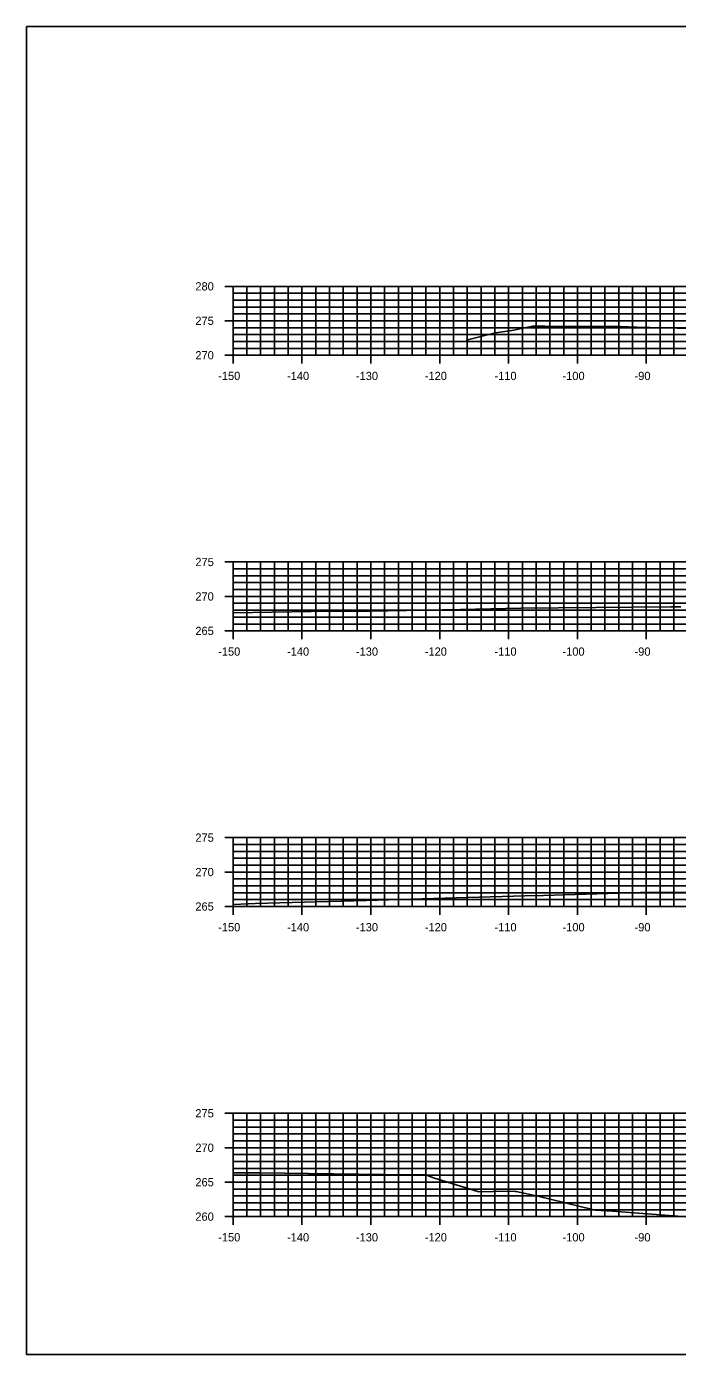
# Model space of a CAD drawing. Extents: x 1661012 to 1662122, y 670053 to 671852.
# Drawn here: x 1661412 to 1661506.5, y 671274.1 to 671466.8 of the extents above; entities that cross this region are included whole.
import ezdxf

# ---------------------------------------------------------------- set-up
doc = ezdxf.new("R2010")
doc.units = 0
for name, color, linetype in [('R_Concrete', 7, 'Continuous'), ('R_Concrete Hidden', 7, 'Continuous'), ('R_Erosion', 7, 'Continuous'), ('R_Exist Surface', 7, 'Continuous'), ('R_Proposed Road', 7, 'Continuous')]:
    doc.layers.add(name, color=color, linetype=linetype)

msp = doc.modelspace()

# ---------------------------------------------------------------- linework, layer by layer
at = {"layer": 'R_Concrete'}
for p, q in [((1661440.79, 671429.12), (1661443.19, 671429.12)), ((1661441.99, 671429.12), (1661741.99, 671429.12)), ((1661441.99, 671419.12), (1661441.99, 671429.12)), ((1661443.99, 671419.12), (1661443.99, 671429.12)), ((1661445.99, 671419.12), (1661445.99, 671429.12)), ((1661447.99, 671419.12), (1661447.99, 671429.12)), ((1661449.99, 671419.12), (1661449.99, 671429.12)), ((1661451.99, 671419.12), (1661451.99, 671429.12)), ((1661453.99, 671419.12), (1661453.99, 671429.12)), ((1661455.99, 671419.12), (1661455.99, 671429.12)), ((1661457.99, 671419.12), (1661457.99, 671429.12)), ((1661459.99, 671419.12), (1661459.99, 671429.12)), ((1661461.99, 671419.12), (1661461.99, 671429.12)), ((1661463.99, 671419.12), (1661463.99, 671429.12)), ((1661465.99, 671419.12), (1661465.99, 671429.12)), ((1661467.99, 671419.12), (1661467.99, 671429.12)), ((1661469.99, 671419.12), (1661469.99, 671429.12)), ((1661471.99, 671419.12), (1661471.99, 671429.12)), ((1661473.99, 671419.12), (1661473.99, 671429.12)), ((1661475.99, 671419.12), (1661475.99, 671429.12)), ((1661477.99, 671419.12), (1661477.99, 671429.12)), ((1661479.99, 671419.12), (1661479.99, 671429.12)), ((1661481.99, 671419.12), (1661481.99, 671429.12)), ((1661483.99, 671419.12), (1661483.99, 671429.12)), ((1661485.99, 671419.12), (1661485.99, 671429.12)), ((1661487.99, 671419.12), (1661487.99, 671429.12)), ((1661489.99, 671419.12), (1661489.99, 671429.12)), ((1661491.99, 671419.12), (1661491.99, 671429.12)), ((1661493.99, 671419.12), (1661493.99, 671429.12)), ((1661495.99, 671419.12), (1661495.99, 671429.12)), ((1661497.99, 671419.12), (1661497.99, 671429.12)), ((1661499.99, 671419.12), (1661499.99, 671429.12)), ((1661501.99, 671419.12), (1661501.99, 671429.12)), ((1661503.99, 671419.12), (1661503.99, 671429.12)), ((1661505.99, 671419.12), (1661505.99, 671429.12)), ((1661441.99, 671428.12), (1661741.99, 671428.12)), ((1661441.99, 671428.12), (1661442.59, 671428.12)), ((1661441.99, 671427.12), (1661741.99, 671427.12)), ((1661441.99, 671427.12), (1661442.59, 671427.12)), ((1661441.99, 671426.12), (1661741.99, 671426.12)), ((1661441.99, 671426.12), (1661442.59, 671426.12)), ((1661441.99, 671425.12), (1661741.99, 671425.12)), ((1661441.99, 671425.12), (1661442.59, 671425.12)), ((1661440.79, 671424.12), (1661443.19, 671424.12)), ((1661441.99, 671424.12), (1661741.99, 671424.12)), ((1661441.99, 671423.12), (1661741.99, 671423.12)), ((1661441.99, 671423.12), (1661442.59, 671423.12)), ((1661441.99, 671422.12), (1661741.99, 671422.12)), ((1661441.99, 671422.12), (1661442.59, 671422.12)), ((1661441.99, 671421.12), (1661741.99, 671421.12)), ((1661441.99, 671421.12), (1661442.59, 671421.12)), ((1661440.79, 671419.12), (1661443.19, 671419.12)), ((1661441.99, 671417.92), (1661441.99, 671420.32)), ((1661441.99, 671420.12), (1661741.99, 671420.12)), ((1661441.99, 671420.12), (1661442.59, 671420.12)), ((1661441.99, 671419.12), (1661741.99, 671419.12)), ((1661443.99, 671419.12), (1661443.99, 671419.72)), ((1661445.99, 671419.12), (1661445.99, 671419.72)), ((1661447.99, 671419.12), (1661447.99, 671419.72)), ((1661449.99, 671419.12), (1661449.99, 671419.72)), ((1661451.99, 671417.92), (1661451.99, 671420.32)), ((1661453.99, 671419.12), (1661453.99, 671419.72)), ((1661455.99, 671419.12), (1661455.99, 671419.72)), ((1661457.99, 671419.12), (1661457.99, 671419.72)), ((1661459.99, 671419.12), (1661459.99, 671419.72)), ((1661461.99, 671417.92), (1661461.99, 671420.32)), ((1661463.99, 671419.12), (1661463.99, 671419.72)), ((1661465.99, 671419.12), (1661465.99, 671419.72)), ((1661467.99, 671419.12), (1661467.99, 671419.72)), ((1661469.99, 671419.12), (1661469.99, 671419.72)), ((1661471.99, 671417.92), (1661471.99, 671420.32)), ((1661473.99, 671419.12), (1661473.99, 671419.72)), ((1661475.99, 671419.12), (1661475.99, 671419.72)), ((1661477.99, 671419.12), (1661477.99, 671419.72)), ((1661479.99, 671419.12), (1661479.99, 671419.72)), ((1661481.99, 671417.92), (1661481.99, 671420.32)), ((1661483.99, 671419.12), (1661483.99, 671419.72)), ((1661485.99, 671419.12), (1661485.99, 671419.72)), ((1661487.99, 671419.12), (1661487.99, 671419.72)), ((1661489.99, 671419.12), (1661489.99, 671419.72)), ((1661491.99, 671417.92), (1661491.99, 671420.32)), ((1661493.99, 671419.12), (1661493.99, 671419.72)), ((1661495.99, 671419.12), (1661495.99, 671419.72)), ((1661497.99, 671419.12), (1661497.99, 671419.72)), ((1661499.99, 671419.12), (1661499.99, 671419.72)), ((1661501.99, 671417.92), (1661501.99, 671420.32)), ((1661503.99, 671419.12), (1661503.99, 671419.72)), ((1661505.99, 671419.12), (1661505.99, 671419.72)), ((1661440.79, 671389.12), (1661443.19, 671389.12)), ((1661441.99, 671389.12), (1661741.99, 671389.12)), ((1661441.99, 671379.12), (1661441.99, 671389.12)), ((1661441.99, 671388.12), (1661741.99, 671388.12)), ((1661441.99, 671388.12), (1661442.59, 671388.12)), ((1661443.99, 671379.12), (1661443.99, 671389.12)), ((1661445.99, 671379.12), (1661445.99, 671389.12)), ((1661447.99, 671379.12), (1661447.99, 671389.12)), ((1661449.99, 671379.12), (1661449.99, 671389.12)), ((1661451.99, 671379.12), (1661451.99, 671389.12)), ((1661453.99, 671379.12), (1661453.99, 671389.12)), ((1661455.99, 671379.12), (1661455.99, 671389.12)), ((1661457.99, 671379.12), (1661457.99, 671389.12)), ((1661459.99, 671379.12), (1661459.99, 671389.12)), ((1661461.99, 671379.12), (1661461.99, 671389.12)), ((1661463.99, 671379.12), (1661463.99, 671389.12)), ((1661465.99, 671379.12), (1661465.99, 671389.12)), ((1661467.99, 671379.12), (1661467.99, 671389.12)), ((1661469.99, 671379.12), (1661469.99, 671389.12)), ((1661471.99, 671379.12), (1661471.99, 671389.12)), ((1661473.99, 671379.12), (1661473.99, 671389.12)), ((1661475.99, 671379.12), (1661475.99, 671389.12)), ((1661477.99, 671379.12), (1661477.99, 671389.12)), ((1661479.99, 671379.12), (1661479.99, 671389.12)), ((1661481.99, 671379.12), (1661481.99, 671389.12)), ((1661483.99, 671379.12), (1661483.99, 671389.12)), ((1661485.99, 671379.12), (1661485.99, 671389.12)), ((1661487.99, 671379.12), (1661487.99, 671389.12)), ((1661489.99, 671379.12), (1661489.99, 671389.12)), ((1661491.99, 671379.12), (1661491.99, 671389.12)), ((1661493.99, 671379.12), (1661493.99, 671389.12)), ((1661495.99, 671379.12), (1661495.99, 671389.12)), ((1661497.99, 671379.12), (1661497.99, 671389.12)), ((1661499.99, 671379.12), (1661499.99, 671389.12)), ((1661501.99, 671379.12), (1661501.99, 671389.12)), ((1661503.99, 671379.12), (1661503.99, 671389.12)), ((1661505.99, 671379.12), (1661505.99, 671389.12)), ((1661441.99, 671387.12), (1661741.99, 671387.12)), ((1661441.99, 671387.12), (1661442.59, 671387.12)), ((1661441.99, 671386.12), (1661741.99, 671386.12)), ((1661441.99, 671386.12), (1661442.59, 671386.12)), ((1661441.99, 671385.12), (1661741.99, 671385.12)), ((1661441.99, 671385.12), (1661442.59, 671385.12)), ((1661440.79, 671384.12), (1661443.19, 671384.12)), ((1661441.99, 671384.12), (1661741.99, 671384.12)), ((1661441.99, 671383.12), (1661741.99, 671383.12)), ((1661441.99, 671383.12), (1661442.59, 671383.12)), ((1661441.99, 671382.12), (1661741.99, 671382.12)), ((1661441.99, 671382.12), (1661442.59, 671382.12)), ((1661441.99, 671381.12), (1661741.99, 671381.12)), ((1661441.99, 671381.12), (1661442.59, 671381.12)), ((1661441.99, 671377.92), (1661441.99, 671380.32)), ((1661451.99, 671377.92), (1661451.99, 671380.32)), ((1661461.99, 671377.92), (1661461.99, 671380.32)), ((1661471.99, 671377.92), (1661471.99, 671380.32)), ((1661481.99, 671377.92), (1661481.99, 671380.32)), ((1661491.99, 671377.92), (1661491.99, 671380.32)), ((1661501.99, 671377.92), (1661501.99, 671380.32)), ((1661440.79, 671379.12), (1661443.19, 671379.12)), ((1661441.99, 671380.12), (1661741.99, 671380.12)), ((1661441.99, 671380.12), (1661442.59, 671380.12)), ((1661441.99, 671379.12), (1661741.99, 671379.12)), ((1661443.99, 671379.12), (1661443.99, 671379.72)), ((1661445.99, 671379.12), (1661445.99, 671379.72)), ((1661447.99, 671379.12), (1661447.99, 671379.72)), ((1661449.99, 671379.12), (1661449.99, 671379.72)), ((1661453.99, 671379.12), (1661453.99, 671379.72)), ((1661455.99, 671379.12), (1661455.99, 671379.72)), ((1661457.99, 671379.12), (1661457.99, 671379.72)), ((1661459.99, 671379.12), (1661459.99, 671379.72)), ((1661463.99, 671379.12), (1661463.99, 671379.72)), ((1661465.99, 671379.12), (1661465.99, 671379.72)), ((1661467.99, 671379.12), (1661467.99, 671379.72)), ((1661469.99, 671379.12), (1661469.99, 671379.72)), ((1661473.99, 671379.12), (1661473.99, 671379.72)), ((1661475.99, 671379.12), (1661475.99, 671379.72)), ((1661477.99, 671379.12), (1661477.99, 671379.72)), ((1661479.99, 671379.12), (1661479.99, 671379.72)), ((1661483.99, 671379.12), (1661483.99, 671379.72)), ((1661485.99, 671379.12), (1661485.99, 671379.72)), ((1661487.99, 671379.12), (1661487.99, 671379.72)), ((1661489.99, 671379.12), (1661489.99, 671379.72)), ((1661493.99, 671379.12), (1661493.99, 671379.72)), ((1661495.99, 671379.12), (1661495.99, 671379.72)), ((1661497.99, 671379.12), (1661497.99, 671379.72)), ((1661499.99, 671379.12), (1661499.99, 671379.72)), ((1661503.99, 671379.12), (1661503.99, 671379.72)), ((1661505.99, 671379.12), (1661505.99, 671379.72)), ((1661440.79, 671349.12), (1661443.19, 671349.12)), ((1661441.99, 671349.12), (1661741.99, 671349.12)), ((1661441.99, 671339.12), (1661441.99, 671349.12)), ((1661441.99, 671348.12), (1661741.99, 671348.12)), ((1661441.99, 671348.12), (1661442.59, 671348.12)), ((1661443.99, 671339.12), (1661443.99, 671349.12)), ((1661445.99, 671339.12), (1661445.99, 671349.12)), ((1661447.99, 671339.12), (1661447.99, 671349.12)), ((1661449.99, 671339.12), (1661449.99, 671349.12)), ((1661451.99, 671339.12), (1661451.99, 671349.12)), ((1661453.99, 671339.12), (1661453.99, 671349.12)), ((1661455.99, 671339.12), (1661455.99, 671349.12)), ((1661457.99, 671339.12), (1661457.99, 671349.12)), ((1661459.99, 671339.12), (1661459.99, 671349.12)), ((1661461.99, 671339.12), (1661461.99, 671349.12)), ((1661463.99, 671339.12), (1661463.99, 671349.12)), ((1661465.99, 671339.12), (1661465.99, 671349.12)), ((1661467.99, 671339.12), (1661467.99, 671349.12)), ((1661469.99, 671339.12), (1661469.99, 671349.12)), ((1661471.99, 671339.12), (1661471.99, 671349.12)), ((1661473.99, 671339.12), (1661473.99, 671349.12)), ((1661475.99, 671339.12), (1661475.99, 671349.12)), ((1661477.99, 671339.12), (1661477.99, 671349.12)), ((1661479.99, 671339.12), (1661479.99, 671349.12)), ((1661481.99, 671339.12), (1661481.99, 671349.12)), ((1661483.99, 671339.12), (1661483.99, 671349.12)), ((1661485.99, 671339.12), (1661485.99, 671349.12)), ((1661487.99, 671339.12), (1661487.99, 671349.12)), ((1661489.99, 671339.12), (1661489.99, 671349.12)), ((1661491.99, 671339.12), (1661491.99, 671349.12)), ((1661493.99, 671339.12), (1661493.99, 671349.12)), ((1661495.99, 671339.12), (1661495.99, 671349.12)), ((1661497.99, 671339.12), (1661497.99, 671349.12)), ((1661499.99, 671339.12), (1661499.99, 671349.12)), ((1661501.99, 671339.12), (1661501.99, 671349.12)), ((1661503.99, 671339.12), (1661503.99, 671349.12)), ((1661505.99, 671339.12), (1661505.99, 671349.12)), ((1661441.99, 671347.12), (1661741.99, 671347.12)), ((1661441.99, 671347.12), (1661442.59, 671347.12)), ((1661441.99, 671346.12), (1661741.99, 671346.12)), ((1661441.99, 671346.12), (1661442.59, 671346.12)), ((1661440.79, 671344.12), (1661443.19, 671344.12)), ((1661441.99, 671345.12), (1661741.99, 671345.12)), ((1661441.99, 671345.12), (1661442.59, 671345.12)), ((1661441.99, 671344.12), (1661741.99, 671344.12)), ((1661441.99, 671343.12), (1661741.99, 671343.12)), ((1661441.99, 671343.12), (1661442.59, 671343.12)), ((1661441.99, 671342.12), (1661741.99, 671342.12)), ((1661441.99, 671342.12), (1661442.59, 671342.12)), ((1661441.99, 671341.12), (1661741.99, 671341.12)), ((1661441.99, 671341.12), (1661442.59, 671341.12)), ((1661441.99, 671337.92), (1661441.99, 671340.32)), ((1661441.99, 671340.12), (1661741.99, 671340.12)), ((1661441.99, 671340.12), (1661442.59, 671340.12)), ((1661451.99, 671337.92), (1661451.99, 671340.32)), ((1661461.99, 671337.92), (1661461.99, 671340.32)), ((1661471.99, 671337.92), (1661471.99, 671340.32)), ((1661481.99, 671337.92), (1661481.99, 671340.32)), ((1661491.99, 671337.92), (1661491.99, 671340.32)), ((1661501.99, 671337.92), (1661501.99, 671340.32)), ((1661440.79, 671339.12), (1661443.19, 671339.12)), ((1661441.99, 671339.12), (1661741.99, 671339.12)), ((1661443.99, 671339.12), (1661443.99, 671339.72)), ((1661445.99, 671339.12), (1661445.99, 671339.72)), ((1661447.99, 671339.12), (1661447.99, 671339.72)), ((1661449.99, 671339.12), (1661449.99, 671339.72)), ((1661453.99, 671339.12), (1661453.99, 671339.72)), ((1661455.99, 671339.12), (1661455.99, 671339.72)), ((1661457.99, 671339.12), (1661457.99, 671339.72)), ((1661459.99, 671339.12), (1661459.99, 671339.72)), ((1661463.99, 671339.12), (1661463.99, 671339.72)), ((1661465.99, 671339.12), (1661465.99, 671339.72)), ((1661467.99, 671339.12), (1661467.99, 671339.72)), ((1661469.99, 671339.12), (1661469.99, 671339.72)), ((1661473.99, 671339.12), (1661473.99, 671339.72)), ((1661475.99, 671339.12), (1661475.99, 671339.72)), ((1661477.99, 671339.12), (1661477.99, 671339.72)), ((1661479.99, 671339.12), (1661479.99, 671339.72)), ((1661483.99, 671339.12), (1661483.99, 671339.72)), ((1661485.99, 671339.12), (1661485.99, 671339.72)), ((1661487.99, 671339.12), (1661487.99, 671339.72)), ((1661489.99, 671339.12), (1661489.99, 671339.72)), ((1661493.99, 671339.12), (1661493.99, 671339.72)), ((1661495.99, 671339.12), (1661495.99, 671339.72)), ((1661497.99, 671339.12), (1661497.99, 671339.72)), ((1661499.99, 671339.12), (1661499.99, 671339.72)), ((1661503.99, 671339.12), (1661503.99, 671339.72)), ((1661505.99, 671339.12), (1661505.99, 671339.72)), ((1661440.79, 671309.12), (1661443.19, 671309.12)), ((1661441.99, 671309.12), (1661741.99, 671309.12)), ((1661441.99, 671294.12), (1661441.99, 671309.12)), ((1661443.99, 671294.12), (1661443.99, 671309.12)), ((1661445.99, 671294.12), (1661445.99, 671309.12)), ((1661447.99, 671294.12), (1661447.99, 671309.12)), ((1661449.99, 671294.12), (1661449.99, 671309.12)), ((1661451.99, 671294.12), (1661451.99, 671309.12)), ((1661453.99, 671294.12), (1661453.99, 671309.12)), ((1661455.99, 671294.12), (1661455.99, 671309.12)), ((1661457.99, 671294.12), (1661457.99, 671309.12)), ((1661459.99, 671294.12), (1661459.99, 671309.12)), ((1661461.99, 671294.12), (1661461.99, 671309.12)), ((1661463.99, 671294.12), (1661463.99, 671309.12)), ((1661465.99, 671294.12), (1661465.99, 671309.12)), ((1661467.99, 671294.12), (1661467.99, 671309.12)), ((1661469.99, 671294.12), (1661469.99, 671309.12)), ((1661471.99, 671294.12), (1661471.99, 671309.12)), ((1661473.99, 671294.12), (1661473.99, 671309.12)), ((1661475.99, 671294.12), (1661475.99, 671309.12)), ((1661477.99, 671294.12), (1661477.99, 671309.12)), ((1661479.99, 671294.12), (1661479.99, 671309.12)), ((1661481.99, 671294.12), (1661481.99, 671309.12)), ((1661483.99, 671294.12), (1661483.99, 671309.12)), ((1661485.99, 671294.12), (1661485.99, 671309.12)), ((1661487.99, 671294.12), (1661487.99, 671309.12)), ((1661489.99, 671294.12), (1661489.99, 671309.12)), ((1661491.99, 671294.12), (1661491.99, 671309.12)), ((1661493.99, 671294.12), (1661493.99, 671309.12)), ((1661495.99, 671294.12), (1661495.99, 671309.12)), ((1661497.99, 671294.12), (1661497.99, 671309.12)), ((1661499.99, 671294.12), (1661499.99, 671309.12)), ((1661501.99, 671294.12), (1661501.99, 671309.12)), ((1661503.99, 671294.12), (1661503.99, 671309.12)), ((1661505.99, 671294.12), (1661505.99, 671309.12)), ((1661441.99, 671308.12), (1661741.99, 671308.12)), ((1661441.99, 671308.12), (1661442.59, 671308.12)), ((1661441.99, 671307.12), (1661741.99, 671307.12)), ((1661441.99, 671307.12), (1661442.59, 671307.12)), ((1661441.99, 671306.12), (1661741.99, 671306.12)), ((1661441.99, 671306.12), (1661442.59, 671306.12)), ((1661440.79, 671304.12), (1661443.19, 671304.12)), ((1661441.99, 671305.12), (1661741.99, 671305.12)), ((1661441.99, 671305.12), (1661442.59, 671305.12)), ((1661441.99, 671304.12), (1661741.99, 671304.12)), ((1661441.99, 671303.12), (1661741.99, 671303.12)), ((1661441.99, 671303.12), (1661442.59, 671303.12)), ((1661441.99, 671302.12), (1661741.99, 671302.12)), ((1661441.99, 671302.12), (1661442.59, 671302.12)), ((1661441.99, 671301.12), (1661741.99, 671301.12)), ((1661441.99, 671301.12), (1661442.59, 671301.12)), ((1661441.99, 671300.12), (1661741.99, 671300.12)), ((1661441.99, 671300.12), (1661442.59, 671300.12)), ((1661440.79, 671299.12), (1661443.19, 671299.12)), ((1661441.99, 671299.12), (1661741.99, 671299.12)), ((1661441.99, 671298.12), (1661741.99, 671298.12)), ((1661441.99, 671298.12), (1661442.59, 671298.12)), ((1661441.99, 671297.12), (1661741.99, 671297.12)), ((1661441.99, 671297.12), (1661442.59, 671297.12)), ((1661441.99, 671296.12), (1661741.99, 671296.12)), ((1661441.99, 671296.12), (1661442.59, 671296.12)), ((1661440.79, 671294.12), (1661443.19, 671294.12)), ((1661441.99, 671292.92), (1661441.99, 671295.32)), ((1661441.99, 671295.12), (1661741.99, 671295.12)), ((1661441.99, 671295.12), (1661442.59, 671295.12)), ((1661441.99, 671294.12), (1661741.99, 671294.12)), ((1661443.99, 671294.12), (1661443.99, 671294.72)), ((1661445.99, 671294.12), (1661445.99, 671294.72)), ((1661447.99, 671294.12), (1661447.99, 671294.72)), ((1661449.99, 671294.12), (1661449.99, 671294.72)), ((1661451.99, 671292.92), (1661451.99, 671295.32)), ((1661453.99, 671294.12), (1661453.99, 671294.72)), ((1661455.99, 671294.12), (1661455.99, 671294.72)), ((1661457.99, 671294.12), (1661457.99, 671294.72)), ((1661459.99, 671294.12), (1661459.99, 671294.72)), ((1661461.99, 671292.92), (1661461.99, 671295.32)), ((1661463.99, 671294.12), (1661463.99, 671294.72)), ((1661465.99, 671294.12), (1661465.99, 671294.72)), ((1661467.99, 671294.12), (1661467.99, 671294.72)), ((1661469.99, 671294.12), (1661469.99, 671294.72)), ((1661471.99, 671292.92), (1661471.99, 671295.32)), ((1661473.99, 671294.12), (1661473.99, 671294.72)), ((1661475.99, 671294.12), (1661475.99, 671294.72)), ((1661477.99, 671294.12), (1661477.99, 671294.72)), ((1661479.99, 671294.12), (1661479.99, 671294.72)), ((1661481.99, 671292.92), (1661481.99, 671295.32)), ((1661483.99, 671294.12), (1661483.99, 671294.72)), ((1661485.99, 671294.12), (1661485.99, 671294.72)), ((1661487.99, 671294.12), (1661487.99, 671294.72)), ((1661489.99, 671294.12), (1661489.99, 671294.72)), ((1661491.99, 671292.92), (1661491.99, 671295.32)), ((1661493.99, 671294.12), (1661493.99, 671294.72)), ((1661495.99, 671294.12), (1661495.99, 671294.72)), ((1661497.99, 671294.12), (1661497.99, 671294.72)), ((1661499.99, 671294.12), (1661499.99, 671294.72)), ((1661501.99, 671292.92), (1661501.99, 671295.32)), ((1661503.99, 671294.12), (1661503.99, 671294.72)), ((1661505.99, 671294.12), (1661505.99, 671294.72))]:
    msp.add_line(p, q, dxfattribs=at)
at = {"layer": 'R_Erosion'}
for points in [[(1661475.81, 671421.32), (1661480.1, 671422.37), (1661482.44, 671422.7), (1661485.53, 671423.33), (1661487.26, 671423.36), (1661489.49, 671423.3), (1661498.2, 671423.28), (1661500.62, 671423.22), (1661522.02, 671422.65)], [(1661441.99, 671381.72), (1661453.34, 671381.93), (1661461.83, 671381.99), (1661475.01, 671382.22), (1661483.78, 671382.43), (1661505.56, 671382.63), (1661506.98, 671382.62)], [(1661441.99, 671339.4), (1661444.16, 671339.51), (1661445.2, 671339.54), (1661461.32, 671339.99), (1661469.42, 671340.22), (1661484.36, 671340.66), (1661487.08, 671340.74), (1661491.67, 671340.88), (1661501.14, 671341.14), (1661505.24, 671341.16), (1661524.29, 671341.18)], [(1661441.99, 671300.49), (1661446.08, 671300.48), (1661452.92, 671300.39), (1661467.47, 671300.2), (1661468.62, 671300.19), (1661469.98, 671300.2), (1661471.08, 671299.76), (1661477.68, 671297.71), (1661481.83, 671297.8), (1661482.93, 671297.77), (1661483.08, 671297.75), (1661486.23, 671297.09), (1661494, 671295.19), (1661494.61, 671295.08), (1661497.1, 671294.91), (1661506.58, 671294.21)]]:
    msp.add_lwpolyline(points, dxfattribs=at)
at = {"layer": 'R_Exist Surface'}
for p, q in [((1661441.99, 671419.12), (1661441.99, 671429.12)), ((1661441.99, 671419.12), (1661741.99, 671419.12)), ((1661441.99, 671379.12), (1661441.99, 671389.12)), ((1661441.99, 671379.12), (1661741.99, 671379.12)), ((1661441.99, 671339.12), (1661441.99, 671349.12)), ((1661441.99, 671339.12), (1661741.99, 671339.12)), ((1661441.99, 671294.12), (1661441.99, 671309.12)), ((1661441.99, 671294.12), (1661741.99, 671294.12))]:
    msp.add_line(p, q, dxfattribs=at)
at = {"layer": 'R_Proposed Road'}
msp.add_lwpolyline([(1661411.99, 671274.12), (1661771.99, 671274.12), (1661771.99, 671466.82), (1661411.99, 671466.82)], close=True, dxfattribs=at)

# ---------------------------------------------------------------- texts
at = {"layer": 'R_Concrete Hidden'}
for s, p in [('280', (1661436.51, 671428.52)), ('275', (1661436.51, 671423.52)), ('270', (1661436.51, 671418.52)), ('-150', (1661439.82, 671415.52)), ('-140', (1661449.82, 671415.52)), ('-130', (1661459.82, 671415.52)), ('-120', (1661469.82, 671415.52)), ('-110', (1661479.94, 671415.52)), ('-100', (1661489.82, 671415.52)), ('-90', (1661500.28, 671415.52)), ('275', (1661436.51, 671388.52)), ('270', (1661436.51, 671383.52)), ('265', (1661436.51, 671378.52)), ('-150', (1661439.82, 671375.52)), ('-140', (1661449.82, 671375.52)), ('-130', (1661459.82, 671375.52)), ('-120', (1661469.82, 671375.52)), ('-110', (1661479.94, 671375.52)), ('-100', (1661489.82, 671375.52)), ('-90', (1661500.28, 671375.52)), ('275', (1661436.51, 671348.52)), ('270', (1661436.51, 671343.52)), ('265', (1661436.51, 671338.52)), ('-150', (1661439.82, 671335.52)), ('-140', (1661449.82, 671335.52)), ('-130', (1661459.82, 671335.52)), ('-120', (1661469.82, 671335.52)), ('-110', (1661479.94, 671335.52)), ('-100', (1661489.82, 671335.52)), ('-90', (1661500.28, 671335.52)), ('275', (1661436.51, 671308.52)), ('270', (1661436.51, 671303.52)), ('265', (1661436.51, 671298.52)), ('260', (1661436.51, 671293.52)), ('-150', (1661439.82, 671290.52)), ('-140', (1661449.82, 671290.52)), ('-130', (1661459.82, 671290.52)), ('-120', (1661469.82, 671290.52)), ('-110', (1661479.94, 671290.52)), ('-100', (1661489.82, 671290.52)), ('-90', (1661500.28, 671290.52))]:
    msp.add_text(s, height=1.2, dxfattribs=at).set_placement(p)
at = {"layer": 'R_Exist Surface'}
for p in [(1661441.99, 671419.12), (1661441.99, 671379.12), (1661441.99, 671339.12), (1661441.99, 671294.12)]:
    msp.add_text('-', height=0.0001, dxfattribs=at).set_placement(p)

doc.saveas('drawing.dxf')
